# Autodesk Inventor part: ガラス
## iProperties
Created: 2001-06
Part Number: ガラス
Document SubType Name: ﾓﾃﾞﾘﾝｸﾞ
Designer: Administrator
Control State: 0
Master: False
Checked Out: False
Shininess: 20.0
Length Units: 11269
Angle Units: 11279
Time Units: 11290
Mass Units: 11283
Length Display Precision: 3
Angle Display Precision: 2
Density: 0.0
Volumn: 0.0
Area: 0.0
PropertySet Name: Model Information
Author: Administrator
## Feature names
1. 押し出し1 [Extrusion]
